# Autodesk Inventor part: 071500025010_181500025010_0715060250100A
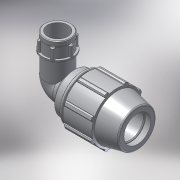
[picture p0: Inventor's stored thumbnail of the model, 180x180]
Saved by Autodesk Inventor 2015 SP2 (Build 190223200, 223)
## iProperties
Created: 2017-02
Part Number: 071500025010_181500025010_0715060250100A
Material: PVC-Piping
Description: PLASSON 90° ELBOW FEMALE ADAPTOR 25-1"
Document SubType Name: Modeling
Designer: KIM
Mass: 92.6774 g
Surface Area: 199.44 cm^2
Volume: 66.1981 cm^3
Density: 1.4 g/cm^3
Appearance: Smooth - White
Author: KIM
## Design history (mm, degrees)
derived "07150.ipt"
feature "Solid1::07150.ipt"
tag "TaggingFeature1"
body "Solid1"
other parameters: "d2" = 25, "d4" = 6.91667, "d5" = 20.75, "d7" = 54, "d9" = 11.85714, "d11" = 2.76667, "d13" = 120 deg, "d14" = 37.5, "d15" = 12 deg, "d16" = 46.98, "d18" = 1.25, "d19" = 35 deg, "d20" = 17.5 deg, "d21" = 50.22, "d23" = 0, "d25" = 360 deg, "d27" = 1.08, "d33" = 0.5, "d42" = 30.71, "d43" = 1.62, "d46" = 0.75, "d51" = 83, "d68" = 2.76667, "d73" = 39.3783, "d74" = 21, "d75" = 45.28505, "d76" = 30.291, "d77" = 23.1, "d79" = 12.1164, "d80" = 0.90873, "d83" = 0, "d84" = 0, "d91" = 40.5, "d93" = 58, "d94" = 30.291, "d95" = 21.2037, "d96" = 8.3, "d97" = 50 deg, "d98" = 27.2619, "d99" = 0.5, "d100" = 0.5, "d101" = 7, "d102" = 39.3783, "d103" = 17.85, "d104" = 0, "d108" = 360 deg, "d110" = 1.18135, "d_" = 25, "E_" = 54, "A_" = 83, "l_" = 58, "l_2" = 21, "Rp_" = 30.291, "d105" = 5.90675
